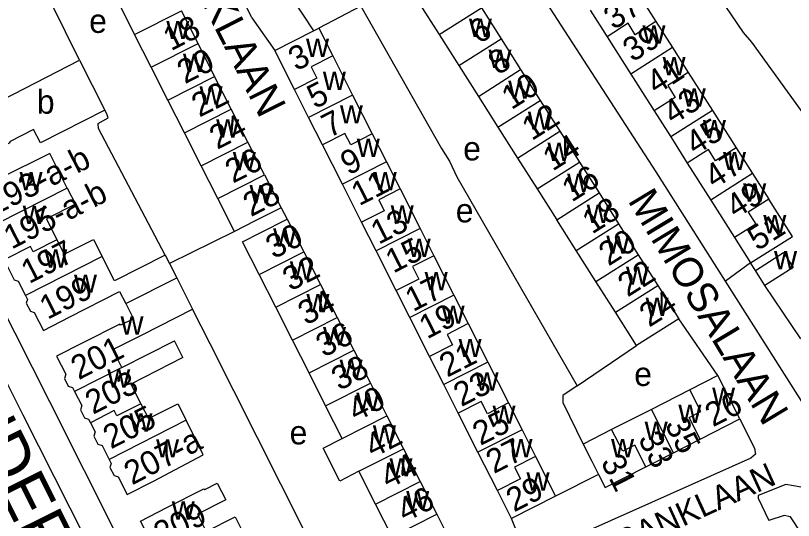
# Model space of a CAD drawing. Extents: x 161258 to 163262, y 380749 to 382054.
# Drawn here: x 162410.3 to 162541.1, y 381533.2 to 381618.1 of the extents above; entities that cross this region are included whole.
import ezdxf

# ---------------------------------------------------------------- set-up
doc = ezdxf.new("R2010")
doc.units = 0
for name, color, linetype in [('BLT_Basislijn', 7, 'Continuous'), ('BLT_Bebouwing', 7, 'Continuous'), ('BLT_Centroide', 7, 'Continuous'), ('BLT_Huisnummer', 7, 'Continuous'), ('BLT_Huisnummer_ tussenligend', 7, 'Continuous'), ('BLT_Huisnummer_reeks', 7, 'Continuous'), ('BLT_Onderverdeling_panden', 7, 'Continuous'), ('BLT_Straatnaam', 7, 'Continuous'), ('BLT_Straatnaam_hoofdweg', 7, 'Continuous'), ('BLT_Straatnaam_verkleind', 7, 'Continuous')]:
    doc.layers.add(name, color=color, linetype=linetype)

msp = doc.modelspace()

# ---------------------------------------------------------------- linework, layer by layer
at = {"layer": 'BLT_Basislijn'}
for p, q in [((162452.43, 381627.73), (162460.41, 381615.47)), ((162468.38, 381619.63), (162461.3, 381615.92)), ((162450.02, 381617.65), (162453.89, 381612.2)), ((162394.91, 381594.92), (162416.03, 381553.18)), ((162390.45, 381592.66), (162411.57, 381550.93)), ((162454.97, 381585.72), (162456, 381583.84)), ((162447.12, 381581.75), (162436.2, 381576.36)), ((162533.86, 381576.46), (162529.64, 381573.39)), ((162534.66, 381575.21), (162533.86, 381576.46)), ((162542.27, 381563.69), (162536.25, 381572.68)), ((162443.04, 381562.88), (162440.07, 381568.69)), ((162528.36, 381557.53), (162521.79, 381567.07)), ((162504.69, 381555.78), (162514.7, 381562.56)), ((162416.03, 381553.18), (162460.34, 381465.23)), ((162411.57, 381550.93), (162455.87, 381462.98)), ((162508.3, 381540.91), (162501.09, 381537.24))]:
    msp.add_line(p, q, dxfattribs=at)
for points in [[(162498.05, 381662.97), (162524.65, 381626.95), (162532.63, 381615.22), (162534, 381613.56), (162552.72, 381587.7), (162564.3, 381596.04)], [(162421.1, 381610.58), (162402.22, 381648.75), (162400.82, 381652.67), (162403.78, 381654.14), (162403, 381656.35)], [(162529.64, 381573.39), (162517.99, 381591.78), (162501.4, 381617.37), (162493.84, 381629.18), (162493.38, 381630.23), (162488.54, 381637.44), (162481.93, 381647.89)], [(162450.02, 381617.65), (162447.64, 381622.65)], [(162468.38, 381619.63), (162481.89, 381595.7), (162483.24, 381593.59), (162484.5, 381590.95), (162504.69, 381555.78)], [(162435.49, 381577.76), (162424.28, 381599.06), (162424.23, 381599.88), (162425.9, 381600.86), (162425.69, 381601.52), (162425.35, 381602.17)], [(162553.41, 381547.25), (162552.71, 381546.74), (162551, 381546.01), (162548.82, 381545.9), (162547.07, 381546.7), (162544.68, 381549.65), (162529.64, 381573.39)], [(162470.57, 381507.75), (162462.89, 381523.46), (162443.04, 381562.88)], [(162504.69, 381555.78), (162502.28, 381554.17), (162502.29, 381552.97), (162505.71, 381546)], [(162532.07, 381550.22), (162534.53, 381545.25), (162534.67, 381544.33), (162533.91, 381543.61), (162500.52, 381528.7), (162498.03, 381528.54), (162495.96, 381529.41), (162494.78, 381530.68), (162493.68, 381533.5)], [(162631.05, 381395.39), (162633.35, 381398.89), (162632.9, 381403.53), (162624.97, 381412.12), (162615.66, 381424.45), (162600, 381449.93), (162569.46, 381500), (162544.3, 381537.15), (162543.02, 381538.49), (162542.38, 381538.78), (162539.8, 381539.21), (162535.12, 381537.37), (162535.12, 381536.9), (162536.9, 381533.15)], [(162549.4, 381496.02), (162556.96, 381500), (162560.62, 381501.86), (162560.84, 381502.53), (162549.84, 381519.11), (162545.67, 381526.01), (162540.54, 381533.77), (162539.48, 381534.01), (162536.9, 381533.15)]]:
    msp.add_lwpolyline(points, dxfattribs=at)
at = {"layer": 'BLT_Bebouwing'}
for p, q in [((162513.9, 381623.43), (162517.95, 381617.04)), ((162430.35, 381614.88), (162427.56, 381620.4)), ((162478.23, 381620.04), (162481.52, 381614.85)), ((162441, 381613.33), (162438.2, 381618.85)), ((162488.63, 381619.35), (162491.92, 381614.16)), ((162506.89, 381618.97), (162509.73, 381614.5)), ((162460.41, 381615.47), (162461.3, 381615.92)), ((162461.3, 381615.92), (162463.64, 381611.29)), ((162517.95, 381617.04), (162520.73, 381612.67)), ((162433.15, 381609.36), (162430.35, 381614.88)), ((162453.89, 381612.2), (162460.41, 381615.47)), ((162481.52, 381614.85), (162484.82, 381609.66)), ((162443.79, 381607.81), (162441, 381613.33)), ((162491.92, 381614.16), (162495.21, 381608.97)), ((162509.73, 381614.5), (162513.72, 381608.21)), ((162457.2, 381605.64), (162453.89, 381612.2)), ((162520.73, 381612.67), (162523.37, 381608.5)), ((162463.64, 381611.29), (162466.98, 381604.69)), ((162484.82, 381609.66), (162488.11, 381604.47)), ((162435.94, 381603.84), (162433.15, 381609.36)), ((162495.21, 381608.97), (162498.5, 381603.78)), ((162513.72, 381608.21), (162517.63, 381602.05)), ((162523.37, 381608.5), (162527.44, 381602.09)), ((162446.59, 381602.29), (162443.79, 381607.81)), ((162459.58, 381600.93), (162457.2, 381605.64)), ((162466.98, 381604.69), (162470.29, 381598.14)), ((162488.11, 381604.47), (162491.4, 381599.28)), ((162438.73, 381598.32), (162435.94, 381603.84)), ((162498.5, 381603.78), (162501.79, 381598.59)), ((162449.38, 381596.77), (162446.59, 381602.29)), ((162517.63, 381602.05), (162520.43, 381597.64)), ((162527.44, 381602.09), (162531.43, 381595.8)), ((162461.91, 381596.34), (162459.58, 381600.93)), ((162491.4, 381599.28), (162494.69, 381594.1)), ((162441.53, 381592.79), (162438.73, 381598.32)), ((162470.29, 381598.14), (162472.66, 381593.46)), ((162501.79, 381598.59), (162505.08, 381593.4)), ((162520.43, 381597.64), (162523.21, 381593.26)), ((162452.17, 381591.25), (162449.38, 381596.77)), ((162465.26, 381589.7), (162461.91, 381596.34)), ((162531.43, 381595.8), (162534.18, 381591.47)), ((162494.69, 381594.1), (162497.98, 381588.91)), ((162444.32, 381587.27), (162441.53, 381592.79)), ((162472.66, 381593.46), (162474.97, 381588.9)), ((162505.08, 381593.4), (162508.38, 381588.22)), ((162523.21, 381593.26), (162527.17, 381587.01)), ((162534.18, 381591.47), (162536.91, 381587.16)), ((162468.49, 381583.3), (162465.26, 381589.7)), ((162474.97, 381588.9), (162478.32, 381582.27)), ((162497.98, 381588.91), (162501.27, 381583.72)), ((162447.12, 381581.75), (162444.32, 381587.27)), ((162508.38, 381588.22), (162511.67, 381583.03)), ((162527.17, 381587.01), (162531.17, 381580.71)), ((162470.92, 381578.51), (162468.49, 381583.3)), ((162504.56, 381578.53), (162501.27, 381583.72)), ((162478.32, 381582.27), (162480.64, 381577.68)), ((162511.67, 381583.03), (162514.96, 381577.84)), ((162531.17, 381580.71), (162533.86, 381576.46)), ((162458.79, 381578.33), (162461.59, 381572.81)), ((162474.31, 381571.81), (162470.92, 381578.51)), ((162507.85, 381573.34), (162504.56, 381578.53)), ((162435.49, 381577.76), (162436.2, 381576.36)), ((162480.64, 381577.68), (162484.01, 381571.03)), ((162514.96, 381577.84), (162518.25, 381572.65)), ((162436.2, 381576.36), (162437.42, 381573.95)), ((162454.06, 381569), (162451.27, 381574.52)), ((162536.25, 381572.68), (162534.66, 381575.21)), ((162437.42, 381573.95), (162440.07, 381568.69)), ((162461.59, 381572.81), (162464.38, 381567.29)), ((162511.15, 381568.16), (162507.85, 381573.34)), ((162476.6, 381567.27), (162474.31, 381571.81)), ((162518.25, 381572.65), (162521.79, 381567.07)), ((162484.01, 381571.03), (162486.42, 381566.26)), ((162456.86, 381563.48), (162454.06, 381569)), ((162514.7, 381562.56), (162511.15, 381568.16)), ((162464.38, 381567.29), (162467.17, 381561.77)), ((162479.9, 381560.74), (162476.6, 381567.27)), ((162486.42, 381566.26), (162489.7, 381559.77)), ((162521.79, 381567.07), (162514.7, 381562.56)), ((162428.2, 381558.9), (162437.05, 381563.34)), ((162438.46, 381560.55), (162437.05, 381563.34)), ((162459.65, 381557.97), (162456.86, 381563.48)), ((162467.17, 381561.77), (162469.96, 381556.26)), ((162482.3, 381556.01), (162479.9, 381560.74)), ((162489.7, 381559.77), (162493.17, 381552.91)), ((162462.44, 381552.45), (162459.65, 381557.97)), ((162532.07, 381550.22), (162528.36, 381557.53)), ((162469.96, 381556.26), (162472.75, 381550.74)), ((162484.72, 381551.22), (162482.3, 381556.01)), ((162523.62, 381555.12), (162517.18, 381551.84)), ((162465.23, 381546.93), (162462.44, 381552.45)), ((162493.17, 381552.91), (162495.45, 381548.41)), ((162472.75, 381550.74), (162475.55, 381545.22)), ((162488.04, 381544.65), (162484.72, 381551.22)), ((162517.18, 381551.84), (162510.5, 381548.44)), ((162525.38, 381546.81), (162532.07, 381550.22)), ((162495.45, 381548.41), (162497.72, 381543.9)), ((162510.5, 381548.44), (162505.71, 381546)), ((162520.89, 381544.53), (162525.38, 381546.81)), ((162475.55, 381545.22), (162478.34, 381539.71)), ((162491.31, 381538.18), (162488.04, 381544.65)), ((162516.26, 381542.17), (162520.89, 381544.53)), ((162497.72, 381543.9), (162501.09, 381537.24)), ((162470.82, 381535.9), (162468.03, 381541.42)), ((162478.34, 381539.71), (162481.13, 381534.19)), ((162493.68, 381533.5), (162491.31, 381538.18)), ((162501.09, 381537.24), (162493.68, 381533.5)), ((162473.61, 381530.38), (162470.82, 381535.9)), ((162481.13, 381534.19), (162483.92, 381528.67))]:
    msp.add_line(p, q, dxfattribs=at)
for points in [[(162408.14, 381603.87), (162421.1, 381610.58)], [(162421.1, 381610.58), (162425.35, 381602.17)], [(162425.35, 381602.17), (162414.51, 381596.66), (162413.36, 381598.92), (162409.31, 381596.82), (162409.4, 381596.64), (162401.37, 381592.56), (162398.22, 381598.75)], [(162419.02, 381589.05), (162416.08, 381594.85), (162407.61, 381590.66), (162403.15, 381588.39), (162404.71, 381585.34), (162404.49, 381584.67), (162405.3, 381583.08), (162406, 381582.85), (162406.17, 381582.51)], [(162452.17, 381591.25), (162454.97, 381585.72)], [(162419.02, 381589.05), (162420.43, 381586.35), (162415.52, 381583.85), (162417.29, 381580.36)], [(162533.86, 381576.46), (162540.89, 381580.9), (162536.91, 381587.16)], [(162454.97, 381585.72), (162450.51, 381583.47), (162447.12, 381581.75)], [(162451.27, 381574.52), (162448.48, 381580.03), (162451.54, 381581.58), (162456, 381583.84)], [(162456, 381583.84), (162458.79, 381578.33)], [(162417.29, 381580.36), (162418.53, 381577.92), (162423.44, 381580.42), (162424.89, 381577.55)], [(162534.66, 381575.21), (162539.37, 381578.21), (162540.98, 381575.68), (162536.25, 381572.68)], [(162408.42, 381576.97), (162410.12, 381573.63), (162410.76, 381573.42), (162412, 381570.99)], [(162435.49, 381577.76), (162426.98, 381573.43), (162424.89, 381577.55)], [(162412, 381570.99), (162412.33, 381570.33), (162412.13, 381569.71), (162412.83, 381568.33), (162413.47, 381568.12), (162415.01, 381565.11), (162419.46, 381567.37), (162427.82, 381571.63), (162428.85, 381569.62)], [(162428.85, 381569.62), (162430.14, 381567.08), (162427.97, 381565.98), (162427.86, 381566.19), (162421.67, 381563.04), (162417.21, 381560.78), (162418.76, 381557.73), (162418.54, 381557.05), (162419.2, 381555.75), (162419.92, 381555.52), (162420.26, 381554.86)], [(162428.2, 381558.9), (162426.68, 381561.88), (162431.61, 381564.39), (162440.07, 381568.69)], [(162438.46, 381560.55), (162429.7, 381556.1), (162431.38, 381552.79)], [(162528.36, 381557.53), (162523.62, 381555.12)], [(162420.26, 381554.86), (162421.48, 381552.46), (162421.25, 381551.77), (162421.94, 381550.4), (162422.61, 381550.18), (162422.91, 381549.59)], [(162431.38, 381552.79), (162432.66, 381550.28), (162437.59, 381552.79), (162439, 381550)], [(162422.91, 381549.59), (162423.7, 381548.04), (162423.48, 381547.35), (162424.17, 381545.99), (162424.89, 381545.75), (162426.09, 381543.41)], [(162426.09, 381543.41), (162426.42, 381542.76), (162426.2, 381542.08), (162426.9, 381540.69), (162427.59, 381540.47), (162429.09, 381537.52), (162433.54, 381539.79), (162441.89, 381544.17), (162439, 381550)], [(162468.03, 381541.42), (162464.82, 381539.77), (162462.05, 381545.31), (162465.23, 381546.93)], [(162505.71, 381546), (162507.16, 381543.15), (162508.3, 381540.91)], [(162508.3, 381540.91), (162509.43, 381538.7), (162516.26, 381542.17)], [(162434.3, 381527.19), (162433.98, 381527.81), (162433.32, 381528.03), (162432.61, 381529.42), (162432.82, 381530.07), (162431.31, 381533.04), (162435.77, 381535.31), (162441.98, 381538.47), (162442.16, 381538.35), (162444.23, 381539.41), (162445.65, 381536.62), (162440.91, 381534.21), (162442.39, 381531.31)], [(162442.39, 381531.31), (162447.23, 381533.77), (162448.66, 381530.94), (162443.85, 381528.49), (162445.35, 381525.55)]]:
    msp.add_lwpolyline(points, dxfattribs=at)
at = {"layer": 'BLT_Onderverdeling_panden'}
for p, q in [((162430.35, 381614.88), (162438.2, 381618.85)), ((162481.52, 381614.85), (162488.63, 381619.35)), ((162433.15, 381609.36), (162441, 381613.33)), ((162484.82, 381609.66), (162491.92, 381614.16)), ((162520.73, 381612.67), (162513.72, 381608.21)), ((162488.11, 381604.47), (162495.21, 381608.97)), ((162435.94, 381603.84), (162443.79, 381607.81)), ((162466.98, 381604.69), (162459.58, 381600.93)), ((162491.4, 381599.28), (162498.5, 381603.78)), ((162438.73, 381598.32), (162446.59, 381602.29)), ((162527.44, 381602.09), (162520.43, 381597.64)), ((162494.69, 381594.1), (162501.79, 381598.59)), ((162441.53, 381592.79), (162449.38, 381596.77)), ((162472.66, 381593.46), (162465.26, 381589.7)), ((162497.98, 381588.91), (162505.08, 381593.4)), ((162444.32, 381587.27), (162452.17, 381591.25)), ((162534.18, 381591.47), (162527.17, 381587.01)), ((162419.02, 381589.05), (162406.17, 381582.51)), ((162501.27, 381583.72), (162508.38, 381588.22)), ((162478.32, 381582.27), (162470.92, 381578.51)), ((162504.56, 381578.53), (162511.67, 381583.03)), ((162451.27, 381574.52), (162458.79, 381578.33)), ((162424.89, 381577.55), (162412, 381570.99)), ((162507.85, 381573.34), (162514.96, 381577.84)), ((162428.85, 381569.62), (162437.42, 381573.95)), ((162454.06, 381569), (162461.59, 381572.81)), ((162511.15, 381568.16), (162518.25, 381572.65)), ((162484.01, 381571.03), (162476.6, 381567.27)), ((162456.86, 381563.48), (162464.38, 381567.29)), ((162459.65, 381557.97), (162467.17, 381561.77)), ((162489.7, 381559.77), (162482.3, 381556.01)), ((162428.2, 381558.9), (162420.26, 381554.86)), ((162462.44, 381552.45), (162469.96, 381556.26)), ((162465.23, 381546.93), (162472.75, 381550.74)), ((162520.89, 381544.53), (162517.18, 381551.84)), ((162439, 381550), (162426.09, 381543.41)), ((162495.45, 381548.41), (162488.04, 381544.65)), ((162468.03, 381541.42), (162475.55, 381545.22)), ((162470.82, 381535.9), (162478.34, 381539.71)), ((162473.61, 381530.38), (162481.13, 381534.19))]:
    msp.add_line(p, q, dxfattribs=at)
for points in [[(162517.95, 381617.04), (162514.48, 381614.84), (162513.27, 381616.75), (162509.73, 381614.5)], [(162463.64, 381611.29), (162459.99, 381609.44), (162460.96, 381607.55), (162457.2, 381605.64)], [(162523.37, 381608.5), (162519.92, 381606.3), (162521.18, 381604.3), (162517.63, 381602.05)], [(162470.29, 381598.14), (162466.67, 381596.3), (162465.68, 381598.25), (162461.91, 381596.34)], [(162531.43, 381595.8), (162527.98, 381593.61), (162526.77, 381595.52), (162523.21, 381593.26)], [(162474.97, 381588.9), (162471.36, 381587.07), (162472.29, 381585.23), (162468.49, 381583.3)], [(162536.91, 381587.16), (162533.47, 381584.98), (162534.74, 381582.98), (162531.17, 381580.71)], [(162417.29, 381580.36), (162413.31, 381578.34), (162412.86, 381579.23), (162408.42, 381576.97)], [(162480.64, 381577.68), (162477.05, 381575.85), (162478.12, 381573.74), (162474.31, 381571.81)], [(162486.42, 381566.26), (162482.85, 381564.45), (162483.74, 381562.69), (162479.9, 381560.74)], [(162525.38, 381546.81), (162523.52, 381550.47), (162525.48, 381551.47), (162523.62, 381555.12)], [(162493.17, 381552.91), (162489.62, 381551.1), (162488.57, 381553.18), (162484.72, 381551.22)], [(162431.38, 381552.79), (162427.35, 381550.73), (162426.9, 381551.63), (162422.91, 381549.59)], [(162516.26, 381542.17), (162514.4, 381545.83), (162512.36, 381544.79), (162510.5, 381548.44)], [(162497.72, 381543.9), (162494.19, 381542.11), (162495.19, 381540.15), (162491.31, 381538.18)]]:
    msp.add_lwpolyline(points, dxfattribs=at)

# ---------------------------------------------------------------- texts
at = {"layer": 'BLT_Centroide'}
for s, p in [('e', (162422.71, 381615.14)), ('w', (162486.52, 381614.47)), ('w', (162435.67, 381614.09)), ('w', (162515.68, 381613.34)), ('w', (162459.15, 381611.09)), ('w', (162489.81, 381609.25)), ('w', (162438.47, 381608.59)), ('w', (162519.06, 381608.03)), ('w', (162461.98, 381605.53)), ('w', (162493.12, 381604.06)), ('b', (162413.92, 381601.56)), ('w', (162441.26, 381603.06)), ('w', (162522.45, 381602.72)), ('w', (162464.84, 381599.91)), ('w', (162496.42, 381598.84)), ('w', (162444.05, 381597.53)), ('w', (162525.84, 381597.41)), ('w', (162467.68, 381594.28)), ('e', (162485.56, 381593.7)), ('w', (162499.72, 381593.62)), ('w', (162446.85, 381592.03)), ('w', (162529.22, 381592.06)), ('w', (162411.01, 381588.69)), ('w', (162470.53, 381588.69)), ('w', (162503.02, 381588.41)), ('w', (162532.61, 381586.75)), ('w', (162449.65, 381586.5)), ('w', (162411.55, 381583)), ('w', (162473.38, 381583.06)), ('e', (162484.31, 381583.28)), ('w', (162506.31, 381583.19)), ('w', (162535.99, 381581.44)), ('w', (162453.63, 381579.19)), ('w', (162509.61, 381578)), ('w', (162476.23, 381577.47)), ('w', (162415.16, 381575.69)), ('w', (162537.8, 381575.38)), ('w', (162456.43, 381573.66)), ('w', (162512.91, 381572.78)), ('w', (162420.16, 381571.44)), ('w', (162479.09, 381571.84)), ('w', (162459.22, 381568.16)), ('w', (162516.21, 381567.56)), ('w', (162481.94, 381566.22)), ('w', (162427.98, 381564.41)), ('w', (162462.01, 381562.62)), ('w', (162484.79, 381560.62)), ('w', (162464.8, 381557.12)), ('w', (162425.75, 381555.5)), ('e', (162514.3, 381555.77)), ('w', (162487.64, 381555)), ('w', (162467.59, 381551.59)), ('w', (162527.39, 381552.44)), ('w', (162490.49, 381549.41)), ('w', (162521.72, 381549.55)), ('w', (162429.48, 381548.09)), ('w', (162516.06, 381546.67)), ('e', (162456.39, 381545.95)), ('w', (162470.39, 381546.06)), ('w', (162433.95, 381543.75)), ('w', (162493.34, 381543.78)), ('w', (162510.41, 381543.78)), ('w', (162473.18, 381540.56)), ('w', (162496.2, 381538.16)), ('w', (162475.98, 381535.03)), ('w', (162436.59, 381533.31))]:
    msp.add_text(s, height=4, dxfattribs=at).set_placement(p)
at = {"layer": 'BLT_Huisnummer'}
for s, rotation, p in [('37', 32.4479, (162510.82, 381615.55)), ('18', 26.8419, (162436.45, 381612.04)), ('6', 32.3327, (162488.2, 381613.16)), ('3', 26.9204, (162457.5, 381608.65)), ('41', 32.4485, (162518, 381604.66)), ('10', 32.3342, (162493.66, 381602.12)), ('22', 26.839, (162441.23, 381600.88)), ('7', 26.9234, (162463.07, 381597.44)), ('45', 32.4515, (162524.57, 381594.47)), ('14', 32.3321, (162500.59, 381591.8)), ('26', 26.8469, (162446.86, 381589.77)), ('11', 26.9263, (162468.07, 381585.97)), ('18', 32.33, (162507.22, 381581.21)), ('51', 32.4853, (162535, 381578.4)), ('30', 26.8567, (162453.7, 381577.05)), ('15', 26.92, (162473.82, 381574.66)), ('199', 26.9698, (162415.7, 381566.87)), ('34', 26.8569, (162459.12, 381565.92)), ('24', 32.3241, (162516.81, 381565.55)), ('19', 26.926, (162479.48, 381563.59)), ('201', 26.9694, (162420.95, 381556.73)), ('38', 26.857, (162464.73, 381554.91)), ('23', 26.9228, (162485.25, 381552.21)), ('26', 26.9724, (162527.52, 381548.8)), ('35', 296.9714, (162519.36, 381549.31)), ('42', 26.8511, (162470.37, 381543.61)), ('31', 296.9738, (162508.61, 381542.99)), ('29', 26.9184, (162494.09, 381534.49)), ('46', 26.8544, (162475.77, 381532.78)), ('209', 26.9686, (162434.87, 381528.85))]:
    msp.add_text(s, height=4, rotation=rotation, dxfattribs=at).set_placement(p)
at = {"layer": 'BLT_Huisnummer_ tussenligend'}
for s, rotation, p in [('39', 32.4479, (162514.03, 381610.14)), ('20', 26.8419, (162438.79, 381606.49)), ('8', 32.3327, (162491.41, 381607.95)), ('5', 26.9204, (162460.64, 381602.3)), ('43', 32.4485, (162520.82, 381599.6)), ('12', 32.3342, (162497.08, 381596.92)), ('24', 26.839, (162444.22, 381595.46)), ('9', 26.9234, (162466.25, 381591.13)), ('47', 32.4515, (162527.76, 381588.84)), ('16', 32.3321, (162503.8, 381586.59)), ('28', 26.8469, (162449.88, 381584.15)), ('49', 32.4515, (162531.37, 381583.83)), ('13', 26.9263, (162471.35, 381579.49)), ('20', 32.33, (162509.98, 381575.84)), ('197', 26.9692, (162412.6, 381572.88)), ('32', 26.8567, (162456.52, 381571.64)), ('22', 32.33, (162513.19, 381570.63)), ('17', 26.92, (162477.13, 381568.19)), ('36', 26.8569, (162462.12, 381560.51)), ('21', 26.926, (162482.87, 381557.15)), ('203', 26.9694, (162423.35, 381550.91)), ('40', 26.857, (162467.52, 381549.69)), ('205', 26.9694, (162426.36, 381545.09)), ('25', 26.9228, (162488.45, 381545.67)), ('33', 296.9738, (162514.88, 381546.9)), ('27', 26.9228, (162490.71, 381540.95)), ('44', 26.8511, (162472.96, 381538.39))]:
    msp.add_text(s, height=4, rotation=rotation, dxfattribs=at).set_placement(p)
at = {"layer": 'BLT_Huisnummer_reeks'}
for s, rotation, p in [('193-a-b', 26.9692, (162406.85, 381584.4)), ('195-a-b', 26.9692, (162409.67, 381578.68)), ('207-a', 27.7016, (162429.92, 381539.03))]:
    msp.add_text(s, height=4, rotation=rotation, dxfattribs=at).set_placement(p)
at = {"layer": 'BLT_Straatnaam'}
for s, rotation, p in [('HEGGERANKLAAN', 296.696, (162424.45, 381654.34)), ('MIMOSALAAN', 301.1281, (162513.13, 381586.95))]:
    msp.add_text(s, height=5, rotation=rotation, dxfattribs=at).set_placement(p)
at = {"layer": 'BLT_Straatnaam_hoofdweg'}
msp.add_text('LEENDERWEG', height=8, rotation=296.5347, dxfattribs=at).set_placement((162391.16, 381570.7))
at = {"layer": 'BLT_Straatnaam_verkleind'}
msp.add_text('HEGGERANKLAAN', height=4, rotation=24.5029, dxfattribs=at).set_placement((162494.6, 381519.38))

doc.saveas('drawing.dxf')
